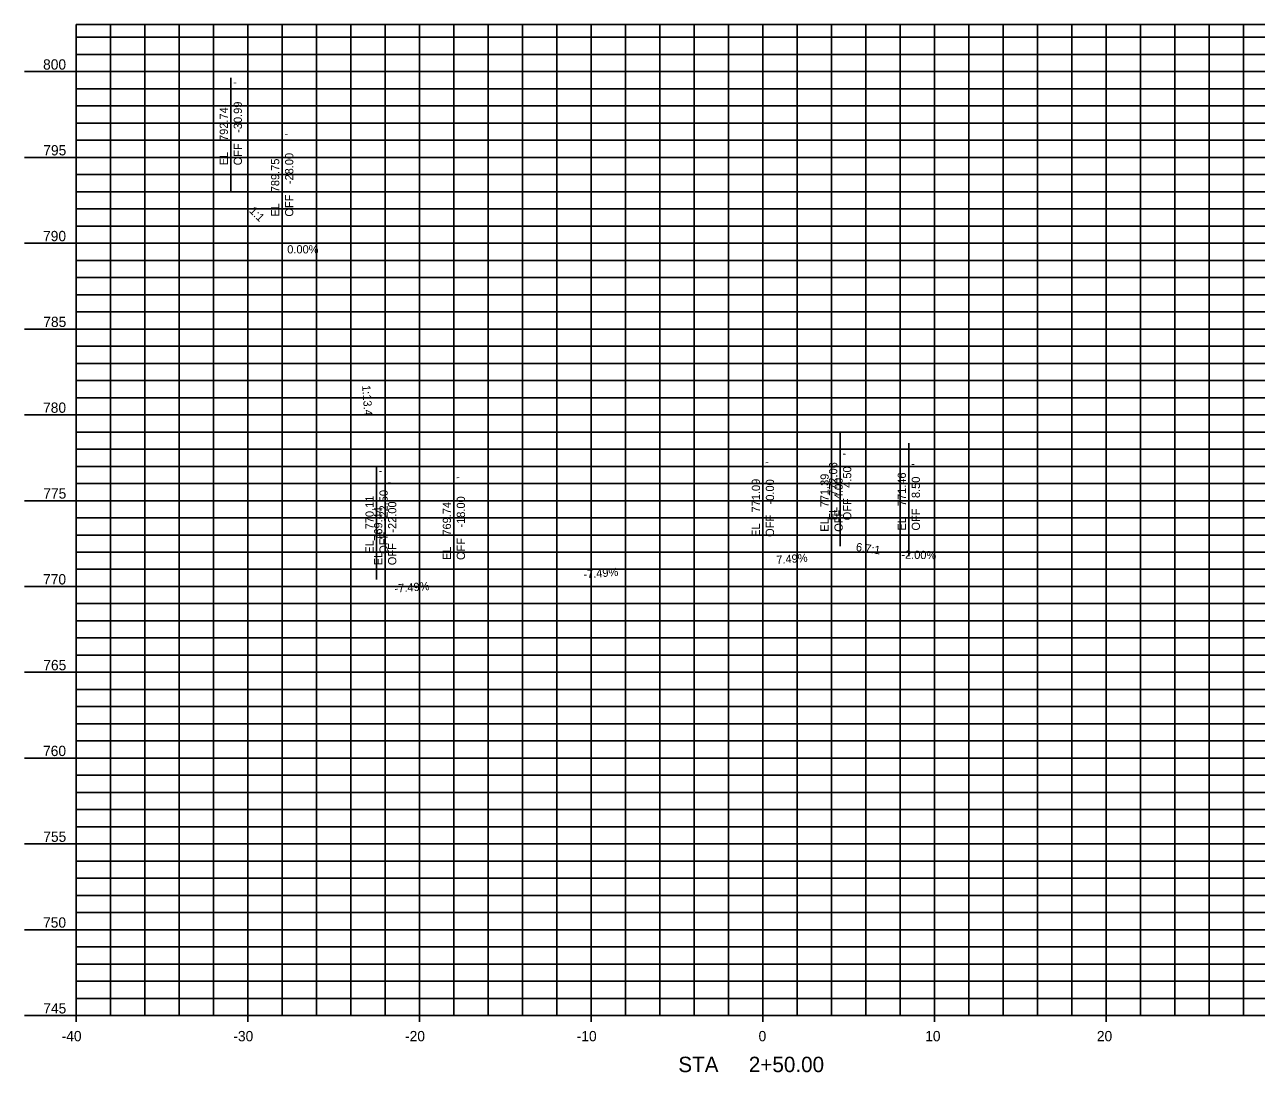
# Model space of a CAD drawing. Extents: x -43 to 103, y 742 to 803.
# Drawn here: x -43 to 28.7, y 741.7 to 802.7 of the extents above; entities that cross this region are included whole.
import ezdxf

# ---------------------------------------------------------------- set-up
doc = ezdxf.new("R2010")
doc.units = 0
for name, color, linetype in [('Default', 7, 'Continuous'), ('XS-Feature Text', 7, 'Continuous'), ('XS-Grid Lines', 7, 'Continuous'), ('XS-Segment Text', 7, 'Continuous'), ('XS-Sheet Major Grid Lines', 7, 'Continuous'), ('XS-Sheet Minor Grid Lines', 7, 'Continuous'), ('XS-Text', 7, 'Continuous')]:
    doc.layers.add(name, color=color, linetype=linetype)

msp = doc.modelspace()

# ---------------------------------------------------------------- linework, layer by layer
at = {"layer": 'XS-Feature Text'}
for p, q in [((-30.99, 793.04), (-30.99, 799.64)), ((-28, 790.05), (-28, 796.65)), ((4.5, 772.357), (4.5, 778.957)), ((0, 771.391), (0, 777.991)), ((4, 771.69), (4, 778.29)), ((8.5, 771.76), (8.5, 778.36)), ((8.5, 771.759), (8.5, 778.359)), ((-22.5, 770.409), (-22.5, 777.009)), ((-22, 769.742), (-22, 776.342)), ((-18, 770.042), (-18, 776.642))]:
    msp.add_line(p, q, dxfattribs=at)
at = {"layer": 'XS-Grid Lines'}
for p, q in [((-40, 802.74), (100, 802.74)), ((-40, 745), (-40, 802.74)), ((-40, 800), (-43, 800)), ((-40, 795), (-43, 795)), ((-40, 790), (-43, 790)), ((-40, 785), (-43, 785)), ((-40, 780), (-43, 780)), ((-40, 775), (-43, 775)), ((-40, 770), (-43, 770)), ((-40, 765), (-43, 765)), ((-40, 760), (-43, 760)), ((-40, 755), (-43, 755)), ((-40, 750), (-43, 750)), ((-40, 745), (-43, 745)), ((-40, 745), (100, 745)), ((-40, 745), (-40, 744.64)), ((-30, 745), (-30, 744.64)), ((-20, 745), (-20, 744.64)), ((-10, 745), (-10, 744.64)), ((0, 745), (0, 744.64)), ((10, 745), (10, 744.64)), ((20, 745), (20, 744.64))]:
    msp.add_line(p, q, dxfattribs=at)
at = {"layer": 'XS-Sheet Major Grid Lines'}
for p, q in [((-30, 745), (-30, 802.74)), ((-20, 745), (-20, 802.74)), ((-10, 745), (-10, 802.74)), ((0, 745), (0, 802.74)), ((10, 745), (10, 802.74)), ((20, 745), (20, 802.74)), ((-40, 800), (100, 800)), ((-40, 795), (100, 795)), ((-40, 790), (100, 790)), ((-40, 785), (100, 785)), ((-40, 780), (100, 780)), ((-40, 775), (100, 775)), ((-40, 770), (100, 770)), ((-40, 765), (100, 765)), ((-40, 760), (100, 760)), ((-40, 755), (100, 755)), ((-40, 750), (100, 750))]:
    msp.add_line(p, q, dxfattribs=at)
at = {"layer": 'XS-Sheet Minor Grid Lines'}
for p, q in [((-38, 745), (-38, 802.74)), ((-36, 745), (-36, 802.74)), ((-34, 745), (-34, 802.74)), ((-32, 745), (-32, 802.74)), ((-28, 745), (-28, 802.74)), ((-26, 745), (-26, 802.74)), ((-24, 745), (-24, 802.74)), ((-22, 745), (-22, 802.74)), ((-18, 745), (-18, 802.74)), ((-16, 745), (-16, 802.74)), ((-14, 745), (-14, 802.74)), ((-12, 745), (-12, 802.74)), ((-8, 745), (-8, 802.74)), ((-6, 745), (-6, 802.74)), ((-4, 745), (-4, 802.74)), ((-2, 745), (-2, 802.74)), ((2, 745), (2, 802.74)), ((4, 745), (4, 802.74)), ((6, 745), (6, 802.74)), ((8, 745), (8, 802.74)), ((12, 745), (12, 802.74)), ((14, 745), (14, 802.74)), ((16, 745), (16, 802.74)), ((18, 745), (18, 802.74)), ((22, 745), (22, 802.74)), ((24, 745), (24, 802.74)), ((26, 745), (26, 802.74)), ((28, 745), (28, 802.74)), ((-40, 802), (100, 802)), ((-40, 801), (100, 801)), ((-40, 799), (100, 799)), ((-40, 798), (100, 798)), ((-40, 797), (100, 797)), ((-40, 796), (100, 796)), ((-40, 794), (100, 794)), ((-40, 793), (100, 793)), ((-40, 792), (100, 792)), ((-40, 791), (100, 791)), ((-40, 789), (100, 789)), ((-40, 788), (100, 788)), ((-40, 787), (100, 787)), ((-40, 786), (100, 786)), ((-40, 784), (100, 784)), ((-40, 783), (100, 783)), ((-40, 782), (100, 782)), ((-40, 781), (100, 781)), ((-40, 779), (100, 779)), ((-40, 778), (100, 778)), ((-40, 777), (100, 777)), ((-40, 776), (100, 776)), ((-40, 774), (100, 774)), ((-40, 773), (100, 773)), ((-40, 772), (100, 772)), ((-40, 771), (100, 771)), ((-40, 769), (100, 769)), ((-40, 768), (100, 768)), ((-40, 767), (100, 767)), ((-40, 766), (100, 766)), ((-40, 764), (100, 764)), ((-40, 763), (100, 763)), ((-40, 762), (100, 762)), ((-40, 761), (100, 761)), ((-40, 759), (100, 759)), ((-40, 758), (100, 758)), ((-40, 757), (100, 757)), ((-40, 756), (100, 756)), ((-40, 754), (100, 754)), ((-40, 753), (100, 753)), ((-40, 752), (100, 752)), ((-40, 751), (100, 751)), ((-40, 749), (100, 749)), ((-40, 748), (100, 748)), ((-40, 747), (100, 747)), ((-40, 746), (100, 746))]:
    msp.add_line(p, q, dxfattribs=at)

# ---------------------------------------------------------------- texts
at = {"layer": 'Default'}
for s, p in [('800', (-41.926, 800.12)), ('795', (-41.913, 795.12)), ('790', (-41.926, 790.12)), ('785', (-41.913, 785.12)), ('780', (-41.926, 780.12)), ('775', (-41.913, 775.12)), ('770', (-41.926, 770.12)), ('765', (-41.913, 765.12)), ('760', (-41.926, 760.12)), ('755', (-41.913, 755.12)), ('750', (-41.926, 750.12)), ('745', (-41.913, 745.12))]:
    msp.add_text(s, height=0.6, dxfattribs=at).set_placement(p)
at = {"layer": 'XS-Feature Text'}
for s, p in [("'", (-30.342, 799.277)), ('792.74', (-31.158, 795.961)), ('-30.99', (-30.342, 796.435)), ("'", (-27.352, 796.286)), ('OFF ', (-30.342, 794.54)), ('EL ', (-31.158, 794.54)), ('789.75', (-28.168, 792.971)), ('-28.00', (-27.352, 793.444)), ('OFF ', (-27.352, 791.55)), ('EL ', (-28.168, 791.55)), ("'", (5.148, 777.646)), ("'", (0.648, 777.153)), ('772.06', (4.332, 775.278)), ("'", (4.648, 776.979)), ('4.50', (5.148, 775.752)), ("'", (9.148, 777.049)), ("'", (9.148, 777.048)), ("'", (-21.852, 776.645)), ("'", (-17.352, 776.278)), ('771.39', (3.832, 774.611)), ('4.00', (4.648, 775.085)), ('771.46', (8.332, 774.681)), ('771.46', (8.332, 774.68)), ('8.50', (9.148, 775.155)), ('8.50', (9.148, 775.153)), ('-22.50', (-21.852, 773.804)), ("'", (-21.352, 775.978)), ('771.09', (-0.168, 774.312)), ('-0.00', (0.648, 774.785)), ('770.11', (-22.668, 773.33)), ('-22.00', (-21.352, 773.137)), ('769.74', (-18.168, 772.963)), ('-18.00', (-17.352, 773.436)), ('OFF ', (5.148, 773.857)), ('769.44', (-22.168, 772.663)), ('OFF ', (0.648, 772.891)), ('EL ', (4.332, 773.857)), ('OFF ', (4.648, 773.19)), ('OFF ', (9.148, 773.26)), ('OFF ', (9.148, 773.259)), ('EL ', (-0.168, 772.891)), ('EL ', (3.832, 773.19)), ('EL ', (8.332, 773.26)), ('EL ', (8.332, 773.259)), ('EL ', (-22.668, 771.909)), ('OFF ', (-21.852, 771.909)), ('OFF ', (-17.352, 771.542)), ('EL ', (-22.168, 771.242)), ('OFF ', (-21.352, 771.242)), ('EL ', (-18.168, 771.542))]:
    msp.add_text(s, height=0.48, rotation=90, dxfattribs=at).set_placement(p)
at = {"layer": 'XS-Segment Text'}
for s, rotation, p in [('1:1', 315, (-29.952, 791.852)), ('0.00%', 360, (-27.704, 789.408)), ('1:13.4', 274.25926, (-23.345, 781.716)), ('6.7:1', 351.4904, (5.394, 772.081)), ('-2.00%', 358.85424, (8.06, 771.625)), ('7.49%', 4.28498, (0.799, 771.308)), ('-7.49%', 4.28498, (-10.437, 770.467)), ('-7.49%', 4.28498, (-21.437, 769.642))]:
    msp.add_text(s, height=0.48, rotation=rotation, dxfattribs=at).set_placement(p)
at = {"layer": 'XS-Text'}
for s, height, p in [('-40', 0.6, (-40.843, 743.5)), ('-30', 0.6, (-30.843, 743.5)), ('-20', 0.6, (-20.843, 743.5)), ('-10', 0.6, (-10.843, 743.5)), ('0', 0.6, (-0.251, 743.5)), ('10', 0.6, (9.453, 743.5)), ('20', 0.6, (19.453, 743.5)), (' STA ', 0.9, (-5.261, 741.7)), ('2+50.00', 0.9, (-0.82, 741.7))]:
    msp.add_text(s, height=height, dxfattribs=at).set_placement(p)

doc.saveas('drawing.dxf')
